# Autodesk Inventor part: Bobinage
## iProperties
Shininess: 64.0
Length Units: 11269
Angle Units: 11279
Time Units: 11290
Mass Units: 11283
Length Display Precision: 3
Angle Display Precision: 2
Compacted: True
Part Number: Bobinage
Document SubType Name: Modeling
Created: 2005-01
Material: Par défaut
Designer: lolo (Laurent Moretti)
Density: 0.0
Volumn: 0.0
Area: 0.0
PropertySet Name: Model Information
Control State: 0
Master: False
Checked Out: False
Author: lolo (Laurent Moretti)
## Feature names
1. Révolution1 [Revolution]
2. Balayage1
3. Symétrie1 [Mirror]
4. Réseau circulaire1 [Circular Pattern]
